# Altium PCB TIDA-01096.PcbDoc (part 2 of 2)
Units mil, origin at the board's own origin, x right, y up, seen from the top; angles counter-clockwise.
Board outline 3070.87 x 3070.87 mil, 2 copper layers (Top Layer, Bottom Layer), stack 62 mil thick; 117 components, 49 nets, 258 pads, 158 vias.
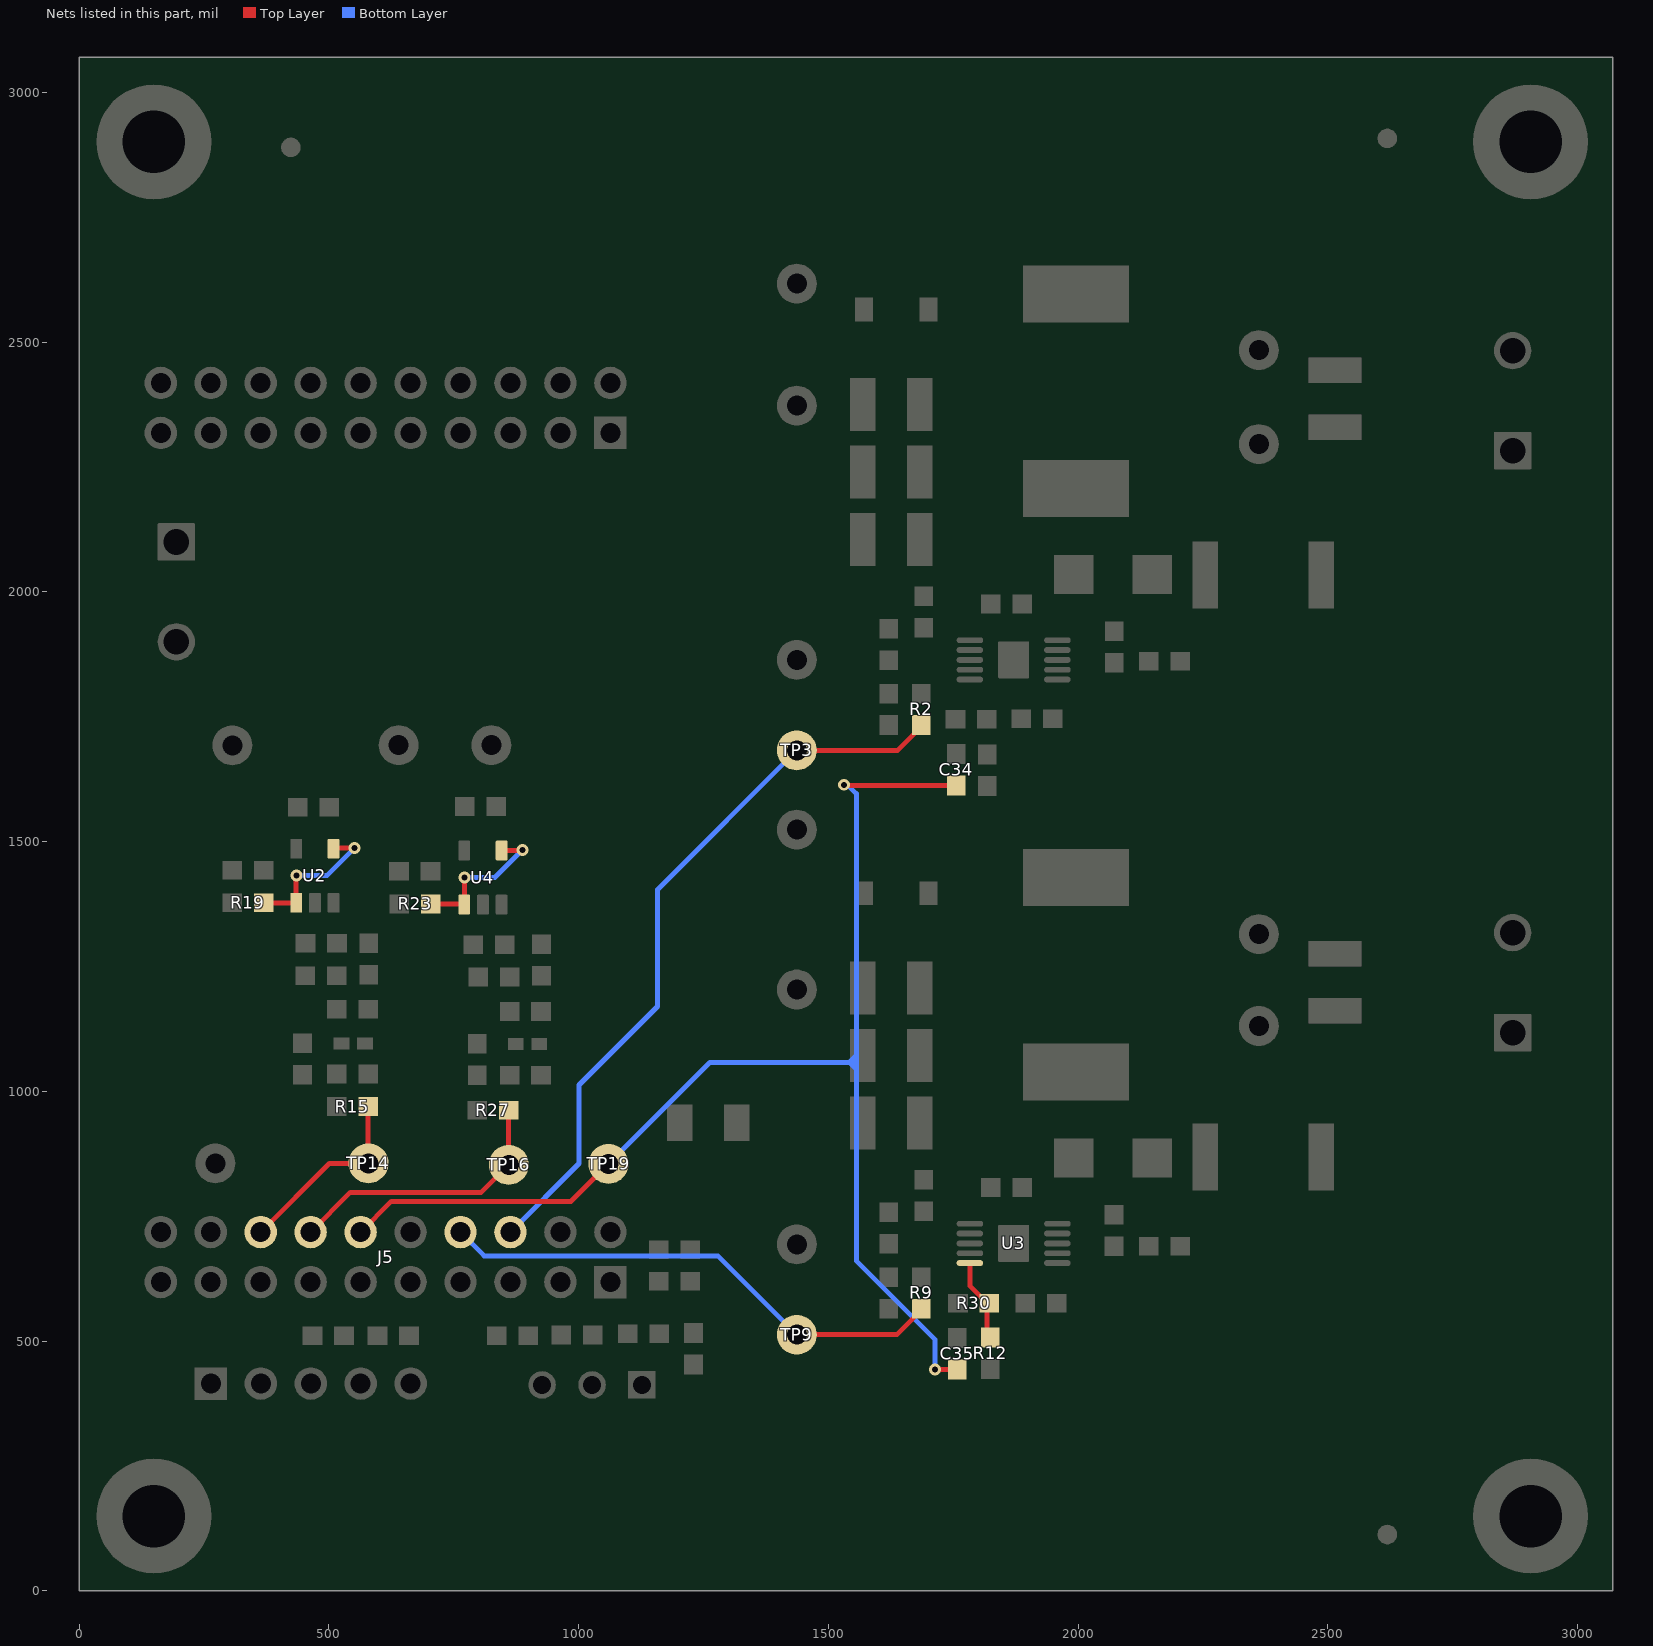
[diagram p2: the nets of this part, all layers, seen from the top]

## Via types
v1: diameter 24, hole 12, Top Layer to Bottom Layer, tented both sides, 148 vias
v2: diameter 19.68, hole 7.87, Top Layer to Bottom Layer, tented both sides, 10 vias

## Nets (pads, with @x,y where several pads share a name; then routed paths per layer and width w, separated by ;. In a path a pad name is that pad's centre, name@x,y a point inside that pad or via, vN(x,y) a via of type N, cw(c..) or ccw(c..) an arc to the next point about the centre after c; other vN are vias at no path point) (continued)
NetR12_2: R12.2 R30.2 U3.5 | length 163.8
  Top Layer w10: U3.5@1783.4,656.43 1783.4,610.89 1817.5,576.8 R12.2@1817.5,506.8
NetR19_1: R19.1 U2.1 U2.4 | length 300.5
  Top Layer w10: R19.1@369.67,1377.82 369.81,1377.69 U2.1@434.81,1377.69 434.81,1431.7 v1(435.15,1432.05) ; U2.4@509.61,1485.96 510.7,1487.05 v1(551.15,1487.05)
  Bottom Layer w10: v1(435.15,1432.05) 496.15,1432.05 v1(551.15,1487.05)
NetR23_1: R23.1 U4.1 U4.4 | length 302.9
  Top Layer w10: R23.1@704.15,1375.3 770.12,1375.3 U4.1@771.25,1374.17 771.25,1428.18 v1(771.6,1428.52) ; U4.4@846.06,1482.43 886.51,1482.43 v1(887.6,1483.52)
  Bottom Layer w10: v1(771.6,1428.52) 832.6,1428.52 v1(887.6,1483.52)
PWM1: J5.6 R2.1 TP3.1 | length 1474
  Top Layer w10: TP3.1@1437,1683 1639,1683 1686,1730 R2.1@1686,1733.5
  Bottom Layer w10: J5.6@863.75,718.43 1001,855.68 1001,1013 1158,1170 1158,1404 TP3.1@1437,1683
PWM2: J5.8 R9.1 TP9.1 | length 1027.6
  Top Layer w10: TP9.1@1437,513 1637.2,513 R9.1@1686,561.8
  Bottom Layer w10: J5.8@763.75,718.43 811.17,671 1279,671 TP9.1@1437,513
PWM_DAC1: J5.16 R15.1 TP14.1 | length 386.6
  Top Layer w10: J5.16@363.75,718.43 501.57,856.25 TP14.1@579.5,856.25 ; TP14.1@578.97,856.78 R15.1@578.97,969.79
  Top Layer w12: TP14.1@578.97,856.78 TP14.1@579.5,856.25
PWM_DAC2: J5.14 R27.1 TP16.1 | length 561.8
  Top Layer w10: J5.14@463.75,718.43 543.32,798 805.25,798 TP16.1@860.5,853.25 ; TP16.1@860,853.75 R27.1@860,962.25
  Top Layer w12: TP16.1@860,853.75 TP16.1@860.5,853.25
SYNC_CLK: C34.2 C35.2 J5.12 TP19.1 | length 2691.1
  Top Layer w10: J5.12@563.75,718.43 625.32,780 985,780 TP19.1@1060,855 ; v1(1531,1614) 1532.5,1612.5 C34.2@1756,1612.5 ; v1(1714.01,443.5) C35.2@1758,443.5
  Bottom Layer w10: TP19.1@1060,855 1263,1058 1556,1058 ; v1(1531,1614) 1538,1614 1556,1596 1556,1058 ; 1542,1058 1556,1072 ; 1543,1058 1556,1045 ; v1(1714.01,443.5) 1714.01,502.99 1556,661 1556,1058
pads on no net: FID1.1 FID2.1 FID3.1 H1.1 H2.1 H3.1 H4.1 H5.0 H6.0 H7.0 H8.0 J5.5 J5.7 J5.9 J5.10 J5.11 J5.13 J5.18 J5.20 J6.1 J6.2 J6.3 J6.4 J6.5 J6.6 J6.7 J6.8 J6.9 J6.10 J6.11 J6.12 J6.13 J6.14 J6.15 J6.16 J6.17 J6.18 J6.19 J6.20

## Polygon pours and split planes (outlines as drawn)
GND on Top Layer "AutoNaming" (solid, remove dead copper, pour order 60): 1279,2009 1277,2065 1221,2009 76,2009 61,2024 61,2720 70,2729 310,2729 320,2739 320,2994 335,3009 336,3010 342,3010 2729,3010 2739,3000 2739,2750 2749,2740 3011,2740 3016,2735 3016,326 3001,311 2741,311 2730,300 2730,45 2726,41 1308,41 1279,70
NetC19_1 on Top Layer "Top Layer-No Net" (solid, remove dead copper, pour order 58): 2323,1245.8 2907,1245.8 2917,1255.8 2917,1366.8 2905,1378.8 2624,1378.8 2581,1378.8 2568,1391.8 2568,1405.8 2568,1426.8 2568,1493.8 2568,1499.37 2567.57,1499.8 2554.57,1512.8 2490,1512.8 1688,1512.8 1681,1505.8 1678,1502.8 1678,1372.8 1678,1367.8 1679,1366.8 1852,1366.8 1856,1362.8 1856,1304.8 1860,1300.8 2306,1300.8 2308,1298.8 2308,1246.8 2309,1245.8
GND on Top Layer "Top Layer-No Net" (solid, remove dead copper, pour order 56): 2076,731.8 2358,731.8 2370,731.8 2380,741.8 2380,931.8 2370,941.8 2275,941.8 2271,945.8 2271,954.8 2271,1271.8 2263,1279.8 1837,1279.8 1834,1282.8 1834,1343.8 1832,1345.8 1660,1345.8 1657,1348.8 1657,1518.8 1654,1521.8 1625,1521.8 1621,1517.8 1621,814.8 1629,806.8 1785,806.8 1790,811.8 1790,851.8 1795,856.8 1839,856.8 1844,861.8 1844,1165.8 1851,1172.8 2103,1172.8 2103,788.8 2096,781.8 2050,781.8 2042,773.8 2042,735.8 2031,724.8 2027,720.8 1994,720.8 1939.74,720.8 1939,720.06 1939,714.28 1942.22,711.06 2036.26,711.06 2057,731.8
NetC19_2 on Top Layer "AutoNaming" (solid, remove dead copper, pour order 54): 2303,1211.8 2910,1211.8 2919,1202.8 2919,1075.8 2909,1065.8 2581,1065.8 2573,1057.8 2573,729.8 2502,658.8 2190,658.8 2181,667.8 2181,708.8 2417,708.8 2451,742.8 2451,1054.8 2440,1065.8 2300,1065.8 2294,1071.8 2294,1202.8
NetC8_2 on Top Layer "AutoNaming" (solid, remove dead copper, pour order 52): 2303,2380 2910,2380 2919,2371 2919,2244 2909,2234 2581,2234 2573,2226 2573,1898 2502,1827 2190,1827 2181,1836 2181,1877 2417,1877 2451,1911 2451,2223 2440,2234 2300,2234 2294,2240 2294,2371
GND on Top Layer "Top Layer-No Net" (solid, remove dead copper, pour order 34): 2076,1900 2358,1900 2370,1900 2380,1910 2380,2100 2370,2110 2275,2110 2271,2114 2271,2123 2271,2440 2263,2448 1837,2448 1834,2451 1834,2512 1832,2514 1660,2514 1657,2517 1657,2687 1654,2690 1625,2690 1621,2686 1621,1983 1629,1975 1785,1975 1790,1980 1790,2020 1795,2025 1839,2025 1844,2030 1844,2334 1851,2341 2103,2341 2103,1957 2096,1950 2050,1950 2042,1942 2042,1904 2031,1893 2027,1889 1994,1889 1939.74,1889 1939,1888.26 1939,1882.48 1942.22,1879.26 2036.26,1879.26 2057,1900
NetC2_1 on Top Layer "Top Layer-No Net" (solid, remove dead copper, pour order 24): 1566.51,2437 1566.51,2316 1566.51,2304.5 1564,2304.5 1516.5,2304.5 1505,2316 1390,2316 1365,2291 1365,1367 1365,1302 1411,1256 1507,1256 1518,1267 1519.52,1268.52 1534.8,1268.52 1566.51,1268.52 1566.51,1135.33 1533.41,1135.33 1517.67,1135.33 1510,1143 1348,1143 1260,1231 1260,1783 1244,1799 80,1799 60,1819 60,1934 80,1954 1242,1954 1256,1968 1260,1972 1260,2025 1260,2365 1332,2437 1503,2437 1516.5,2450.5 1566.49,2450.5
GND1 on Top Layer "Top Layer-No Net" (solid, remove dead copper, pour order 32): 1189,1778 1233,1734 1233,822 1258,797 1258,679 1258,71 1227,40 503.42,40 374,40 354.42,59.58 354.42,308.58 340,323 77,323 60,340 60,412 60,1762 76,1778
NetC2_1 on Top Layer "Top Layer-No Net" (solid, remove dead copper, pour order 18): 1695,1905 1535,1905 1515,1925 1515,2610 1521,2616 1595,2616 1600,2611 1600,2365 1600,1975 1610,1965 1620,1955 1670,1955 1715,1955 1720,1950 1720,1905 1736.74,1888.26 1812.96,1888.26 1812.96,1879.26 1720.74,1879.26
NetC1_2 on Top Layer "Top Layer-No Net" (solid, remove dead copper, pour order 22): 1865,1984 1865,2316 1869,2320 2099,2320 2112,2307 2112,2142 2066,2096 2062,2092 2060,2090 2060,1997 2060,1991 2055,1986 2008,1986 2000,1978 2000,1899 1997,1896 1933.91,1896 1930.96,1898.96 1930.96,1938.04 1926,1943 1871,1943 1865,1949
NetC8_1 on Top Layer "Top Layer-No Net" (solid, remove dead copper, pour order 25): 2323,2414 2907,2414 2917,2424 2917,2535 2905,2547 2624,2547 2581,2547 2568,2560 2568,2574 2568,2595 2568,2662 2568,2667.57 2567.57,2668 2554.57,2681 2490,2681 1688,2681 1681,2674 1678,2671 1678,2541 1678,2536 1679,2535 1852,2535 1856,2531 1856,2473 1860,2469 2306,2469 2308,2467 2308,2415 2309,2414
NetC11_2 on Top Layer "Top Layer-No Net" (solid, remove dead copper, pour order 19): 1865,815.8 1865,1147.8 1869,1151.8 2087,1151.8 2103,1135.8 2103,964.8 2066,927.8 2062,923.8 2060,921.8 2060,828.8 2060,822.8 2055,817.8 2008,817.8 2000,809.8 2000,730.8 1997,727.8 1933.91,727.8 1930.96,730.76 1930.96,769.84 1926,774.8 1871,774.8 1865,780.8
GND on Top Layer "Top Layer-No Net" (solid, remove dead copper, pour order 30): 1621,1477 1621,1498 1615,1504 1496,1504 1408,1504 1402,1510 1402,1536 1409,1543 1410,1544 1497,1544 1648,1544 1657,1535 1657,1517.8 1657,1478 1656,1477
NetC2_1 on Top Layer "Top Layer-No Net" (solid, remove dead copper, pour order 17): 1695,736.8 1535,736.8 1515,756.8 1515,1441.8 1521,1447.8 1595,1447.8 1600,1442.8 1600,1196.8 1600,806.8 1610,796.8 1620,786.8 1670,786.8 1715,786.8 1720,781.8 1720,736.8 1736.74,720.06 1812.96,720.06 1812.96,711.06 1720.74,711.06
GND on Bottom Layer "AutoNaming" (solid, remove dead copper, pour order 50): 507,1799 81,1799 61,1819 61,2720 70,2729 310,2729 320,2739 320,2994 335,3009 336,3010 342,3010 2729,3010 2739,3000 2739,2750 2749,2740 3011,2740 3016,2735 3016,326 3001,311 2741,311 2730,300 2730,45 2726,41 1308,41 1279,70 1279,1790 1270,1799
NetC19_2 on Bottom Layer "AutoNaming" (solid, remove dead copper, pour order 48): 2269,1210 2258,1210 2255,1207 2253.91,1205.91 2253.91,1196 2253.91,1079.09 2260,1073 2268,1065 2886,1065 2911,1065 2921,1075 2921,1202 2913,1210 2269,1210
NetC8_2 on Bottom Layer "AutoNaming" (solid, remove dead copper, pour order 46): 2267,2379 2256,2379 2253,2376 2251.91,2374.91 2251.91,2365 2251.91,2248.09 2258,2242 2266,2234 2884,2234 2909,2234 2919,2244 2919,2371 2911,2379 2267,2379
NetC19_1 on Bottom Layer "AutoNaming" (solid, remove dead copper, pour order 44): 2907.2,1246 2918,1256.8 2918,1368.8 2905,1381.8 2260,1381.8 2252,1373.8 2252,1246
NetC8_1 on Bottom Layer "AutoNaming" (solid, remove dead copper, pour order 42): 2260,2414 2903,2414 2918,2429 2918,2534 2905,2547 2260,2547 2252,2539 2252,2420 2258,2414
GND1 on Bottom Layer "Top Layer-No Net" (solid, remove dead copper, pour order 31): 1189,1778 1233,1734 1233,822 1258,797 1258,679 1258,71 1227,40 503.42,40 374,40 354.42,59.58 354.42,308.58 340,323 77,323 60,340 60,412 60,1762 76,1778

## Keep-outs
Keep-Out Layer:
  lines w12: 20,20 3036,20 3036,3031 20,3031 20,20
  text ".Layer_Name" at -265.1,-1454.89 h60

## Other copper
Top Layer:
  text ".layer_Name" at -250.1,-1444.39 h60
Bottom Layer:
  text ".Layer_Name" at -191.1,-1454.39 h60

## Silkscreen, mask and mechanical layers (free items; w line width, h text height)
Top Overlay:
  lines w6: 1847.02,1716.46 1847.54,1716.46 1873,1691 ; 1852.02,547.26 1878,521.28
  text "LED+" at 2321,2603 h30
  text "GND" at 1278,2579 h30
  text "VIN" at 1284,2323 h30
  text "LED-" at 2324,2144 h30
  text "34V,700mA" at 2673,2119 h30
  text "GND" at 411,2079 h30
  text "LED STRING1" at 2657,2063 h30
  text "VIN" at 418,1908 h30
  text "35 to 42V DC" at 414,1852 h30
  text "UVLO1" at 1239,1819 h30
  text "IADJ2" at 580,1769 h30
  text "+3.3V" at 763,1760 h30
  text "IADJ1" at 113,1635 h30
  text "PWM1" at 1264,1633 h30
  text "GND" at 1280,1485 h30
  text "LED+" at 2320,1435 h30
  text "VIN" at 1279,1142 h30
  text "LED-" at 2323,982 h30
  text "34V,700mA" at 2689,961 h30
  text "LED STRING2" at 2673,910 h30
  text "SYNC_CLK" at 1128,821 h30
  text "GND1" at 103,814 h30
  text "PWM_DAC1" at 493,767 h25
  text "PWM_DAC2" at 776.14,764.69 h25
  text "UVLO2" at 1364,624 h30 r90
  text "PWM2" at 1366,457 h30 r90
  text "SCL" at 279,269 h30 r90
  text "INT" at 384,269 h30 r90
  text "SDA" at 486,268 h30 r90
  text "OUT" at 1041,265 h30 r90
  text "GND" at 938,264 h30 r90
  text "GND" at 684,262 h30 r90
  text "+3.3V" at 583,215 h30 r90
  text "+3.3V" at 1145,213 h30 r90
  text "LMT84" at 974,163 h30
  text "OPT3001" at 430,158 h30
  text "Temp Sensor" at 899,113 h30
  text "Ambient Light Sensor" at 286,110 h30
  text "TIDA-01096-E1" at 1532,96 h60
  text ".layer_Name" at -224.1,-1442.39 h60
Bottom Overlay:
  text ".Layer_Name" at -265.1,-1454.89 h60
Top Paste:
  text ".Layer_Name" at -277.1,-1457.89 h60
Bottom Paste:
  text ".Layer_Name" at -277.1,-1457.89 h60
Top Solder:
  text ".Layer_Name" at -249.1,-1465.39 h60
Bottom Solder:
  text ".Layer_Name" at -202.1,-1461.39 h60
M1 Board Outline:
  the board outline again, w12
M2 Board Dimensions:
  rectangle: -247.6,-601.39 127.4,-476.39
  lines w6: -372.6,-351.39 377.4,-351.39 627.4,-351.39
  lines w7: -372.6,-351.39 -372.6,-601.39 627.4,-601.39 627.4,-351.39 ; -247.6,-601.39 -247.6,-351.39 ; -122.6,-601.39 -122.6,-351.39 ; 127.4,-601.39 127.4,-351.39 ; 377.4,-601.39 377.4,-351.39
  lines w10: -372.6,-666.39 -372.6,-646.39 ; -312.6,-676.39 -372.6,-656.39 ; -312.6,-636.39 -372.6,-656.39 ; -148.52,-656.39 -372.6,-656.39 ; 403.32,-656.39 627.4,-656.39 ; 567.4,-676.39 627.4,-656.39 ; 567.4,-636.39 627.4,-656.39 ; 627.4,-666.39 627.4,-646.39
  text "1000 (mil)" at -138.52,-692.38 h60
M3 3D STEP Top:
  text ".Layer_Name" at -265.1,-1454.89 h60
M4 3D STEP Bottom:
  lines w10: 103.71,753.58 103.71,558.58 1129.71,558.58 ; 105.71,2451.58 105.71,2256.58 1131.71,2256.58 1131.71,2448.58 108.71,2448.58 ; 106.71,750.58 1129.71,750.58
  lines w11.81: -683.69,361.58 3056.46,361.58 3056.46,2684.42 -683.69,2684.42 -683.69,361.58
  text ".Layer_Name" at -265.1,-1454.89 h60
M5 Assembly Top:
  circle w10: c1128,413.43 r15.94
  circle w10: c435,1357 r9.06
  circle w10: c772,1353 r9.06
  lines w12: -1134.1,-1526.56 5465.9,-1526.56 ; -1134.1,-1323.23 5467.9,-1323.23 ; -1134.1,-1119.89 -1134.1,-1729.89 2870.9,-1729.89 5467.9,-1729.89 5467.9,-1119.89 -1133.6,-1119.89 -1133.6,-1729.89 ; 1330.9,-1729.89 1330.9,-1119.89 ; 2597.9,-1323.23 2597.9,-1119.89 ; 3437.9,-1323.23 3437.9,-1119.89 ; 4059.9,-1736.39 4059.9,-1533.56
  text "COMPONENTS MARKED 'DNP' SHOULD NOT BE POPULATED." at 311.4,-914.89 h30
  text "ASSEMBLY VARIANT:" at 310.9,-1030.39 h30
  text ".VariantName" at 1346.9,-1030.39 h30
  text "ALL ARTWORK VIEWED FROM TOP SIDE" at -1070.6,-1252.06 h30
  text "BOARD #:" at 1405.9,-1252.06 h30
  text ".PRJ_Number" at 1951.4,-1252.06 h30
  text "REV:" at 2795.9,-1252.06 h30
  text ".PCB_Rev" at 3087.4,-1252.06 h30
  text "SVN REV:" at 3633.9,-1252.06 h30
  text ".VersionControl_RevNumber" at 4139.9,-1252.06 h30
  text ".layer_Name" at -307.1,-1434.39 h30
  text "LAYER NAME =" at -1077.1,-1441.39 h30
  text "TID #:" at 1410.9,-1452.06 h30
  text ".PRJ_Number" at 1781.4,-1452.06 h30
  text ".plot_File_Name" at -1079.1,-1630.39 h30
  text "GENERATED    :" at 1407.9,-1660.73 h30
  text ".Print_Date" at 2277.4,-1660.73 h30
  text ".Print_Time" at 3006.4,-1660.73 h30
  text "TEXAS INSTRUMENTS" at 4270.9,-1660.73 h30
M6 Assembly Bottom:
  lines w6: -1134.6,-1323.73 5467.4,-1323.73 ; -1132.6,-1527.06 5467.4,-1527.06 ; 895.4,-1323.73 895.4,-1120.39 ; 1735.4,-1323.73 1735.4,-1120.39 ; 3002.4,-1730.39 3002.4,-1120.39 ; 3891.4,-1730.39 5466.9,-1730.39 5466.9,-1120.39 -1134.6,-1120.39 -1134.6,-1730.39 1462.4,-1730.39 5467.4,-1730.39 5467.4,-1120.39
  text "COMPONENTS MARKED 'DNP' SHOULD NOT BE POPULATED." at 5259.9,-914.39 h30
  text ".VariantName" at 4215.9,-1030.39 h30
  text "ASSEMBLY VARIANT:" at 5254.9,-1030.39 h30
  text "SVN REV:" at 699.4,-1252.56 h30
  text ".PCB_Rev" at 1245.9,-1252.56 h30
  text "REV:" at 1537.4,-1252.56 h30
  text ".PRJ_Number" at 2381.9,-1252.56 h30
  text "BOARD #:" at 2927.4,-1252.56 h30
  text "PCB VIEWED FROM BOTTOM SIDE" at 5403.9,-1252.56 h30
  text "Not in version control" at 262,-1255 h30
  text "LAYER NAME =" at 5398.9,-1437.39 h30
  text ".Layer_Name" at 4625.9,-1444.39 h30
  text ".PRJ_Number" at 2378.6,-1447.06 h30
  text "TID #:" at 2904.1,-1452.06 h30
  text "IGNORE ->" at 1705.75,-1454.89 h30
  text ".Print_Time" at 1326.9,-1661.23 h30
  text ".Print_Date" at 2055.9,-1661.23 h30
  text "GENERATED    :" at 2925.4,-1661.23 h30
  text ".plot_File_Name" at 4598.4,-1661.23 h30
  text "PLOT NAME =" at 5403.9,-1661.23 h30
M9 Title Sheet:
  drawing of 57 lines, arcs and shapes, not listed
  text "1" at -102.26,7440.11 h70
  text "2" at 2393.4,7440.11 h70
  text "3" at 4882.74,7440.11 h70
  text "4" at 7389.41,7440.11 h70
  text "5" at 9888.4,7440.11 h70
  text "6" at 12393.4,7440.11 h70
  text "A" at -1258.6,6297.11 h70
  text "A" at 13541.4,6297.11 h70
  text "B" at -1258.6,3917.11 h70
  text "B" at 13541.4,3917.11 h70
  text "C" at -1258.6,1542.11 h70
  text "C" at 13541.4,1542.11 h70
  text "PROJECT TITLE:" at 10501.4,-318.89 h45
  text ".PRJ_Title" at 10564.18,-452.49 h70
  text "DESIGNED FOR:" at 10501.4,-619.89 h45
  text ".PRJ_Customer" at 10551.4,-759.89 h70
  text "D" at -1258.6,-827.89 h70
  text "D" at 13541.4,-827.89 h70
  text "FILE NAME:" at 10501.4,-919.89 h45
  text ".PCB_File_Name_No_Path" at 10832.9,-1045.39 h70
  text "Texas Instruments (TI) and/or its licensors do not warrant the accuracy or completeness of this specification" at 5531.9,-1201.73 h45
  text "ENGINEER:" at 10501.4,-1209.89 h45
  text "LAYOUT BY:" at 12006.4,-1209.89 h45
  text "or any information contained therein. TI and/or its licensors do not warrant that this design will meet" at 5486.91,-1314.4 h45
  text ".PRJ_Engineer" at 10551.4,-1364.88 h50
  text ".PCB_Layout" at 12056.9,-1364.88 h70
  text "the specifications, will be suitable for your application or fit for any particular purpose, or will operate in" at 5486.91,-1427.06 h45
  text "ALTIUM DESIGNER VERSION:" at 12006.4,-1519.89 h45
  text "an implementation. TI and/or its licensors do not warrant that the design is production worthy. You should" at 5486.91,-1539.73 h45
  text "completely validate and test your design implementation to confirm the system functionality for your application." at 5531.9,-1652.39 h45
  text ".print_Scale" at 10551.4,-1653.22 h70
  text ".Application_BuildNumber" at 12056.9,-1653.22 h70
  text "2" at 2393.4,-1859.89 h70
  text "3" at 4882.74,-1859.89 h70
  text "4" at 7389.41,-1859.89 h70
  text "5" at 9888.4,-1859.89 h70
  text "6" at 12393.4,-1859.89 h70
M10 Fab Notes:
  drawing of 228 lines, arcs and shapes, not listed
  text "DESIGN INFORMATION" at 11538.92,6213.61 h60
  text "(REFER ALSO ARRAY/PANEL PROFILING INFORMATION)" at 11177.36,6051.89 h60
  text "BOARD SIZE" at 10491.36,6047.61 h60
  text "78MM" at 10953.68,5919.79 h60
  text "X" at 11459.36,5919.79 h60
  text "78MM" at 11690.68,5919.79 h60
  text "Number of Layers :" at 10894.36,5722.61 h60
  text "2" at 11989.17,5712.61 h60
  text "MIN. TRACK WIDTH:" at 10894.36,5583.61 h60
  text "10" at 11990.6,5583.61 h60
  text "MIL" at 12145.36,5583.61 h60
  text "7.8" at 11949,5468.43 h60
  text "MIN. CLEARANCE:" at 10894.36,5451.61 h60
  text "MIL" at 12145.36,5451.61 h60
  text "7.874" at 11844,5321 h60
  text "MIN. VIA DRILL SIZE:" at 10894.36,5319.61 h60
  text "MIL" at 12145.36,5319.61 h60
  text "5.9055 MIL" at 11589.36,5177.9 h60
  text "MINIMUM ANNULAR RING" at 10565.13,5173.61 h60
  text "EXTERNAL" at 12297.36,5173.61 h60
  text "PER" at 10765.13,5055.61 h60
  text "IPC-D-275 CLASS 2 LEVEL C" at 10985.13,5055.61 h60
  text "MIL, HOLES" at 12473.36,4943.32 h60
  text "+/-" at 12080.9,4942.61 h60
  text "+/-" at 12934.9,4942.61 h60
  text "REGISTRATION TOLERANCES:" at 10565.13,4937.61 h60
  text "METAL" at 11764.9,4937.61 h60
  text "5" at 12341.1,4937.61 h60
  text "3" at 13174.1,4937.61 h60
  text "MIL" at 13290.36,4937.61 h60
  text "MATERIAL:" at 10490.36,4728.15 h60
  text "FR-4 High Tg" at 11476.8,4587.82 h60
  text "FR-408" at 10911.36,4579.25 h60
  text "X" at 11317.9,4579.61 h60
  text "OTHER" at 12399.36,4579.25 h60
  text "63 MIL (1.6mm) +/-10%" at 11231.46,4416.53 h60
  text "THICKNESS:" at 10565.13,4412.25 h60
  text "X" at 11103.3,4412.25 h60
  text "OTHER" at 12516.36,4412.25 h60
  text "TOLERANCE:" at 10565.13,4254.25 h60
  text "X" at 11404.43,4254.25 h60
  text "ANSI IPC-6012 TYPE 3 CLASS 2" at 11591.38,4254.25 h60
  text "OTHER +/-" at 11591.36,4098.25 h60
  text "BOW & TWIST:" at 10565.13,3941.25 h60
  text "X" at 11404.43,3941.25 h60
  text "ANSI IPC-6012 TYPE 3 CLASS 2" at 11591.38,3941.25 h60
  text "OTHER +/-" at 11591.36,3782.74 h60
  text "COPPER THICKNESS (FINISHED):" at 10490.36,3647.25 h60
  text "1.4MIL (1oz)" at 11370.36,3494.53 h60
  text "2MIL (1.4oz)" at 12137.36,3494.53 h60
  text "2.8MIL (2oz)" at 12864.36,3494.53 h60
  text "OUTER:" at 10847.36,3490.25 h60
  text "X" at 11241.9,3489.61 h60
  text "1.4MIL (1oz)" at 11370.36,3337.53 h60
  text "2.8MIL (2oz)" at 12137.36,3337.53 h60
  text "N/A" at 12863.9,3337.89 h60
  text "X" at 12728.9,3334.61 h60
  text "INNER SIGNAL:" at 10558.28,3333.25 h60
  text "DRILLING:" at 10490.36,3194.25 h60
  text "REFERENCE:" at 10565.13,3077.25 h60
  text "X" at 11213.36,3077.25 h60
  text "AS SHOWN" at 11400.36,3077.25 h60
  text "X" at 12114.36,3077.25 h60
  text "NC_DRILL FILES" at 12251.36,3077.25 h60
  text "PTH MIN COPPER THICKNESS:" at 10565.13,2919.25 h60
  text "X" at 11915.36,2919.25 h60
  text "1MIL" at 12052.36,2919.25 h60
  text "OTHER" at 12549.36,2919.25 h60
  text "BOARD FINISH:" at 10490.36,2760.25 h60
  text "SILKSCREEN:" at 10645.58,2642.25 h60
  text "X" at 11594.36,2642.25 h60
  text "TOP" at 11720.36,2642.25 h60
  text "X" at 12104.36,2642.25 h60
  text "BOTTOM" at 12231.36,2642.25 h60
  text "SILKSCREEN COLOR:" at 10645.58,2475.25 h60
  text "X" at 11593.32,2475.25 h60
  text "WHITE" at 11720.36,2475.25 h60
  text "OTHER" at 12231.36,2475.25 h60
  text "SOLDER RESIST COLOR:" at 10645.58,2305.25 h60
  text "X" at 11213.32,2146.05 h60
  text "GREEN" at 11340.36,2146.05 h60
  text "BLUE" at 11931.36,2146.05 h60
  text "OTHER" at 12469.36,2146.05 h60
  text "IMMERSION GOLD (ENIG)" at 11551.36,1957.53 h60
  text "ENEPIG" at 12888.9,1954.25 h60
  text "SURFACE FINISH:" at 10490.36,1953.25 h60
  text "X" at 11364.41,1953.25 h60
  text "IMM. TIN/SILVER OR EQUIV" at 10819.9,1796.25 h60
  text "OTHER" at 12251.36,1796.25 h60
  text "ARRAY/PANEL:" at 10490.36,1617.25 h60
  text "CUT AND TRIM PER MECH LAYER 1" at 11551.36,1612.96 h60
  text "N.C. ROUTE" at 11551.36,1461.25 h60
  text "X" at 12230.36,1461.25 h60
  text "V. SCORE" at 12417.36,1461.25 h60
  text "CERTIFICATION:" at 10490.36,1324.25 h60
  text "MATERIALS AND WORKMANSHIP FOR ALL PCBS" at 11215.36,1324.25 h60
  text "TO MEET OR EXCEED THE REQUIREMENTS OF:" at 11215.36,1226.25 h60
  text "X" at 10841.86,1089.74 h60
  text "ANSI IPC-A-600F CLASS ->" at 10980.86,1089.74 h60
  text "X" at 12619.92,1089.74 h60
  text "2" at 12738.86,1089.74 h60
  text "1" at 12423.86,1088.25 h60
  text "3" at 13092.86,1088.25 h60
  text "X" at 10843.92,930.25 h60
  text "UL 94V-0" at 10980.86,930.25 h60
  text "X" at 11655.92,930.25 h60
  text "RoHS" at 11792.86,930.25 h60
  text "OTHER" at 12437.26,930.25 h60
  text "PER ORDER" at 12834.32,930.25 h60
  text "X" at 12466,803 h60
  text "VIA TENTING:" at 11707.9,796.61 h60
  text "ADDITIONAL REQUIREMENTS:" at 10490.36,789.25 h60
  text "YES" at 12257.57,787.53 h60
  text "NO" at 12622.37,782.3 h60
  text "MICROSECTION:" at 10565.13,674.25 h60
  text "YES" at 11470.86,674.25 h60
  text "IMPEDANCE CONTROL:" at 11729.9,667.61 h60
  text "YES" at 12713.9,666.61 h60
  text "X" at 13255.9,659.61 h60
  text "NO" at 13089.37,649.3 h60
  text "REQUIRED" at 12332.36,518.1 h60
  text "BARE BOARD ELEC. TEST:" at 10565.13,515.25 h60
  text "NONE" at 11870.86,515.25 h60
  text "X" at 12205.36,515.25 h60
  text "PER ORDER" at 12924.36,515.25 h60
  text "MANUFACTURER'S UL:" at 10565.13,358.25 h60
  text "RAIL" at 11730.86,353.96 h60
  text "METAL" at 12222.67,353.96 h60
  text "X" at 12597.9,353.61 h60
  text "SILK" at 12734.36,353.96 h60
M11 Gerber Information:
  lines w12: -1134.1,-1526.56 5465.9,-1526.56 ; -1134.1,-1323.23 5467.9,-1323.23 ; -1134.1,-1119.89 -1134.1,-1729.89 2870.9,-1729.89 5467.9,-1729.89 5467.9,-1119.89 -1133.6,-1119.89 -1133.6,-1729.89 ; 1330.9,-1729.89 1330.9,-1119.89 ; 2597.9,-1323.23 2597.9,-1119.89 ; 3437.9,-1323.23 3437.9,-1119.89 ; 4059.9,-1736.39 4059.9,-1533.56
  text ".PRJ_Number" at 1886.18,-1246.49 h40
  text "BOARD #:" at 1405.9,-1252.06 h60
  text "REV:" at 2795.9,-1252.06 h60
  text ".PCB_Rev" at 3087.4,-1252.06 h60
  text "SVN REV:" at 3633.9,-1252.06 h60
  text ".VersionControl_RevNumber" at 4139.9,-1252.06 h60
  text "ALL ARTWORK VIEWED FROM TOP SIDE" at -1071.6,-1258.06 h60
  text "LAYER NAME =" at -1073.1,-1441.39 h60
  text ".PRJ_Number" at 1766.18,-1456.49 h40
  text "TID #:" at 1400.9,-1462.06 h60
  text ".plot_File_Name" at -1081.1,-1640.39 h60
  text "GENERATED    :" at 1407.9,-1660.73 h60
  text ".Print_Date" at 2277.4,-1660.73 h60
  text ".Print_Time" at 3006.4,-1660.73 h60
  text "TEXAS INSTRUMENTS" at 4270.9,-1660.73 h60
M12 Stackup:
  lines w6: 10517.9,6863.61 13067.9,6863.61 ; 10517.9,6968.01 13067.9,6968.01 ; 10457.9,6378.61 ccw(c10491.9,6378.61) 10491.9,6344.61 13093.9,6344.61 ccw(c13093.9,6378.61) 13127.9,6378.61 13127.9,7084.61 ccw(c13093.9,7084.61) 13093.9,7118.61 10491.9,7118.61 ccw(c10491.9,7084.61) 10457.9,7084.61 10457.9,6378.61
  text "Layer Stack Up Detail for: TIDA-01096-E1" at 10486.18,7003.51 h57
  text "Layer" at 10517.9,6929.01 h24
  text "Gerber" at 11413.71,6929.01 h24
  text "Copper" at 11977.23,6929.01 h24
  text "Dielectric" at 12579.94,6929.01 h24
  text "Name" at 10517.9,6881.01 h24
  text "Document" at 11413.71,6881.01 h24
  text "Thickness" at 11977.23,6881.01 h24
  text "Material" at 12579.94,6881.01 h24
  text "Top Solder Mask" at 10532.9,6789.61 h34
  text "(.GTS)" at 11413.71,6788.05 h34
  text "Solder Resist" at 12579.94,6788.05 h34
  text "Top Layer" at 10527.9,6694.61 h34
  text "(.GTL)" at 11413.71,6691.3 h34
  text "1.4mil" at 11977.23,6691.3 h34
  text "FR4-High Tg" at 12608.9,6690.61 h34
  text "FR4-High Tg" at 12613.9,6465.61 h34
  text "Bottom Layer" at 10522.9,6464.61 h34
  text "(.GBL)" at 11421.9,6460.61 h34
  text "1.4mil" at 11981.9,6454.61 h34
  text "Solder Resist" at 12573.9,6387.61 h34
  text "(.GBS)" at 11418.9,6380.61 h34
  text "Bottom Solder Mask" at 10527.9,6379.61 h34
M13 Component Bodies Top:
  text ".Layer_Name" at -265.1,-1454.89 h60
M14 Component Bodies Bottom:
  text ".Layer_Name" at -265.1,-1454.89 h60
M15 Courtyards Top:
  text ".Layer_Name" at -265.1,-1454.89 h60
M16 Courtyards Bottom:
  text ".Layer_Name" at -265.1,-1454.89 h60
Drill Drawing:
  text ".legend" at 4324.9,1231.61 h60
  text "Drill Table" at 4321.9,1060.61 h60
  text "FOR 7.874MIL DRILL +0/-7.874MIL" at 4321.9,896.61 h60
  text "FOR 12MIL DRILL +0/-12MIL" at 4321.9,791.61 h60
  text "FOR PTH DRILL +/-3MIL" at 4328.18,685.51 h60
  text ".layer_Name" at -160.1,-1438.39 h60

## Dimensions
3070.87,3070.87 to 3070.87,0 on M2 Board Dimensions
0,0 to 3070.87,0 on M2 Board Dimensions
